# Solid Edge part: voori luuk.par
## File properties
Author: Mac
Template: Normal.par
Last saved by: Mac
Revision: 3
Application: Solid Edge
Material: Epoxy, cast rigid
Face Style: White
Fill Style: ANSI34(Plastic)
Virtual Style: Shiny resin yellow
Coef. of Thermal Exp: 5.9e-05
Thermal Conductivity: 2.1
Specific Heat: 0.0
Modulus of Elasticity: 3102640650.0
Poission's Ratio: 0.37
Yield Stress: 65500191.5
Ultimate Stress: 0.0
Elongation: 0.0
Density: 1300,000 kg/m^3
Accuracy: 0,990
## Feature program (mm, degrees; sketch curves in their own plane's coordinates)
sketch for "ExtrudedProtrusion_1" plane through (0, 0, 0.4) normal (0, 0, 1) x-axis (1, 0, 0)
  arc centre (-3.9746, 4.0164) radius 0.5024 from (-3.9746, 4.5188) to (-4.477, 4.0164) ccw
  line (-4.477, 4.0164) -> (-4.477, -3.7836)
  arc centre (-3.9746, -3.7836) radius 0.5024 from (-3.9746, -4.286) to (-4.477, -3.7836) cw
  line (3.8254, -4.286) -> (-3.9746, -4.286)
  arc centre (3.8254, -3.7836) radius 0.5024 from (4.3277, -3.7836) to (3.8254, -4.286) cw
  line (4.3277, -3.7836) -> (4.3277, 4.0164)
  arc centre (3.8254, 4.0164) radius 0.5024 from (4.3277, 4.0164) to (3.8254, 4.5188) ccw
  line (3.8254, 4.5188) -> (-3.9746, 4.5188)
extrude "ExtrudedProtrusion_1" add finite 0.33 along -normal  Profile_Plane1_Distance = 0.4 mm
fillet "Round_1" radius 0.1
thinwall "Thinwall_1"  Thickness = 0.1 mm
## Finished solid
Body 1: solid body, 27 faces, 64 edges, 40 vertices.
  Faces by surface: cylinder 12, plane 11, torus 4
  Edges by curve: line 36, circle 28
Bounding box of the edges (mm; curved faces can reach further): 8.805 x 8.805 x 0.330, from (-4.477, -4.286, 0.07) to (4.3277, 4.5188, 0.4).
Cylindrical faces by radius (mm): R0.1 x4, R0.4024 x4, R0.5024 x4
Toroidal faces (ring radius, tube radius in mm): R0.4024 r0.1 x4
Planar faces by outward normal: +x 2, +y 2, +z 1, -x 2, -y 2, -z 2
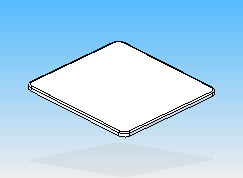
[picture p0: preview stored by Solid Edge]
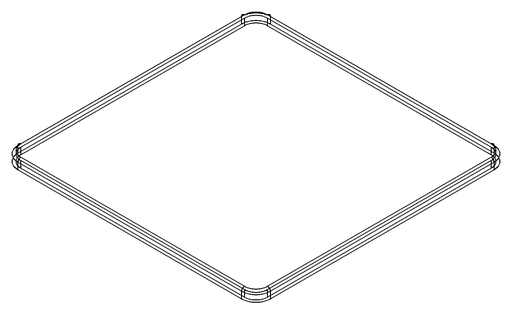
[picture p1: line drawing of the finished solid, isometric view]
